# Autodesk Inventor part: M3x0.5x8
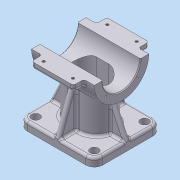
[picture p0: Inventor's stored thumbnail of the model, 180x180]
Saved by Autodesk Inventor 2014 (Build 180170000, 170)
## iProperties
Company: 한국ATC센터
Created: 2009-02
Part Number: M3x0.5x8
Document SubType Name: Modeling
Designer: KYOUNG IL JANG
Density: 2.71 g/cm^3
Material: 알루미늄-6061
Vendor: CBT Solutions
Appearance: 알루미늄 - 평지
Mass: 478.978 g
Surface Area: 471.043 cm^2
Volume: 176.745 cm^3
Author: KYOUNG IL JANG
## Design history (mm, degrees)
sketch "스케치1"
  geometry: L1 (-45, 40)-(45, 40); L2 (45, 40)-(45, -40); L3 (45, -40)-(-45, -40); L4 (-45, -40)-(-45, 40); 3 further points
  constraints: 8 end point, 2 midpoint, 2 parallel, 1 horizontal, 1 horizontal alignment, 1 perpendicular, 1 vertical alignment
  dimensions: "d0" = 90 distance of L2.end L3.end; "d1" = 80 distance of L1.end L2.end
extrude "돌출1" new body sketch "스케치1" distance "d2" = 10; taper "d3" = 0 deg
sketch "스케치2"
  geometry: L1 (40, 0)-(-40, 0) reference; C1 r 32.5 at (0, 80); 2 further points
  constraints: 1 centre point, 1 midpoint, 1 vertical alignment
  dimensions: "d4" = 65 diameter of C1; "d5" = 80 distance from line of C1.centre L1
extrude "돌출2" join sketch "스케치2" stored distance "d6" = 75; taper "d7" = 0 deg
sketch "스케치3"
  geometry: L1 (-7.5, -20)-(7.5, -20); L2 (7.5, 20)-(-7.5, 20); A1 r 20 centre (7.5, 0) between (7.5, -20) and (7.5, 20); A2 r 20 centre (-7.5, 0) between (-7.5, 20) and (-7.5, -20); 2 further points
  constraints: 4 end point, 4 point on circle, 4 tangent, 2 centre point, 1 horizontal, 1 horizontal alignment, 1 midpoint, 1 parallel, 1 vertical alignment
  dimensions: "d8" = 20 radius of A2; "d9" = 55 dimension on A1 A2
extrude "돌출3" join sketch "스케치3" stored distance "d10" = 75; taper "d11" = 0 deg
fillet "모깎기1" dims "d12" = 10
sketch "스케치4"
  geometry: L1 (-45, 0)-(-45, 10) reference; L2 (37.5, 47.5)-(-37.5, 47.5) reference; L3 (-45, 10)-(-27.513, 47.5); 1 further point
  constraints: 2 end point, 1 point on line
  dimensions: "d13" = 25 deg angle of L3 L1
sketch "스케치5"
  geometry: L1 (-40, 0)-(-40, 10) reference; L2 (-40, 10)-(-22.912, 56.95); 2 further points
  constraints: 2 end point, 2 other
  dimensions: "d14" = 20 deg angle of L2 L1
feature "리브1" dims "d15" = 1, "d16" = 6, "d17" = 0
feature "리브2" dims "d18" = 1, "d19" = 6, "d20" = 0
fillet "모깎기2" dims "d21" = 3
fillet "모깎기3" dims "d22" = 3
fillet "모깎기4" dims "d23" = 3
fillet "모깎기5" dims "d24" = 3
fillet "모깎기6" dims "d25" = 3
fillet "모깎기7" dims "d26" = 3
fillet "모깎기8" dims "d27" = 3
sketch "스케치6"
  geometry: A1 r 10 centre (35, -30) between (35, -40) and (45, -30) reference; 1 further point
hole "구멍1" sketch "스케치6" at (35, -30) diameter "d28" = 10; stored, may be unused: countersink angle "d32" = 90 deg, drill point angle "d34" = 118 deg; dims "d29" = 6, "d30" = 4, "d31" = 2, "d33" = 8
hole "구멍2" diameter "d37" = 45; stored, may be unused: countersink angle "d41" = 90 deg, drill point angle "d43" = 118 deg; dims "d35" = 10, "d36" = 10, "d38" = 6, "d39" = 4, "d40" = 2, "d42" = 8
sketch "스케치7"
  geometry: C1 r 22.5 at (0, 0) reference; 2 further points
  dimensions: "d44" = 135 deg dimension on C1.centre point (-18.738, 18.738) point (80, 0); "d45" = 26.5 distance of point (-18.738, 18.738) C1.centre
hole "구멍3" sketch "스케치7" at (-18.738, 18.738) diameter "d46" = 2.459; stored, may be unused: countersink angle "d50" = 90 deg, drill point angle "d52" = 118 deg; dims "d47" = 8, "d48" = 4, "d49" = 2, "d51" = 10
node "작업 평면1"
sketch "스케치8"
  geometry: C1 r 10 at (0, 0); 1 further point
  constraints: 1 centre point, 1 coincident
  dimensions: "d57" = 20 diameter of C1
extrude "돌출4" join sketch "스케치8" stored distance "d58" = 75; taper "d59" = 0 deg
hole "구멍4" diameter "d62" = 8.376; stored, may be unused: countersink angle "d66" = 90 deg, drill point angle "d68" = 118 deg; dims "d60" = 10, "d61" = 10, "d63" = 7, "d64" = 4, "d65" = 2, "d67" = 10
chamfer "모따기1" distance "d69" = 1; stored, may be unused: second distance "d70" = 2, angle "d71" = 45 deg
fillet "모깎기9" dims "d72" = 3
sketch "스케치9"
  geometry: L1 (-31.623, 87.5)-(-45, 87.5); L2 (-45, 87.5)-(-45, 72.5); L3 (-45, 72.5)-(-31.623, 72.5); A1 r 32.5 centre (0, 80) between (-31.623, 87.5) and (-31.623, 72.5) reference; 1 further point
  constraints: 6 end point, 2 parallel, 2 point on circle, 1 horizontal, 1 perpendicular
  dimensions: "d73" = 15 distance of L1.end L2.end; "d74" = 45 distance from line of A1.centre L2
extrude "돌출5" join sketch "스케치9" stored distance "d75" = 50; taper "d76" = 0 deg
fillet "모깎기10" dims "d77" = 3
fillet "모깎기11" dims "d78" = 3
sketch "스케치10"
  geometry: L1 (-61.625, 62.366)-(0, 62.366); L2 (0, 62.366)-(0, -62.366); L3 (0, -62.366)-(-61.625, -62.366); L4 (-61.625, -62.366)-(-61.625, 62.366); C1 r 32.5 at (0, 0) reference; 2 further points
  constraints: 8 end point, 2 parallel, 1 coincident, 1 horizontal, 1 midpoint, 1 perpendicular
extrude "돌출6" cut sketch "스케치10" stored distance "d79" = 10; taper "d80" = 0 deg
node "작업 평면2"
sketch "스케치11"
  geometry: L1 (-7.5, -15)-(7.5, -15); L2 (7.5, 15)-(-7.5, 15); A1 r 20 centre (-7.5, 0) between (-7.5, 20) and (-26.807, 5.217) reference; A2 r 20 centre (7.5, 0) between (26.807, 5.217) and (7.5, 20) reference; A3 r 15 centre (7.5, 0) between (7.5, -15) and (7.5, 15); A4 r 15 centre (-7.5, 0) between (-7.5, 15) and (-7.5, -15); 1 further point
  constraints: 4 end point, 4 point on circle, 3 tangent, 2 centre point, 2 coincident, 1 horizontal, 1 parallel
  dimensions: "d82" = 15 radius of A4
extrude "돌출7" cut sketch "스케치11" stored distance "d83" = 10; taper "d84" = 0 deg
sketch "스케치12"
  geometry: 1 further point
hole "구멍5" sketch "스케치12" at (0, 0) diameter "d85" = 12; stored, may be unused: countersink angle "d89" = 90 deg, drill point angle "d91" = 118 deg; dims "d86" = 6, "d87" = 38, "d88" = 10, "d90" = 8
sketch "스케치13"
  geometry: L1 (-15.5, -12.5)-(-59.5, -12.5) reference; 3 further points
  constraints: 1 horizontal alignment
  dimensions: "d92" = 35 distance of point (-20, -5.5) point (-55, -5.5); "d93" = 17.5 horizontal distance of point (-37.5, 32.5) point (-55, -5.5) (= 0.5 x d92); "d94" = 7 distance from line of L1 point (-55, -5.5)
hole "구멍6" sketch "스케치13" at (-55, -5.5), (-20, -5.5) diameter "d95" = 3.242; stored, may be unused: countersink angle "d99" = 90 deg, drill point angle "d101" = 118 deg; dims "d96" = 6, "d97" = 38, "d98" = 10, "d100" = 8
sketch "스케치14"
  geometry: C1 r 10 at (0, 0); 1 further point
  constraints: 1 centre point, 1 coincident
  dimensions: "d102" = 20 diameter of C1
extrude "돌출8" cut sketch "스케치14" distance "d103" = 5; taper "d104" = 0 deg
node "솔리드1"
mirror "대칭1"
mirror "대칭2"
mirror "대칭3"
mirror "대칭4"
pattern_circular "원형 패턴1" dims angle "d54" = 360 deg
mirror "대칭5"
mirror "대칭6"
mirror "대칭7"
other parameters: "d56" = -117
